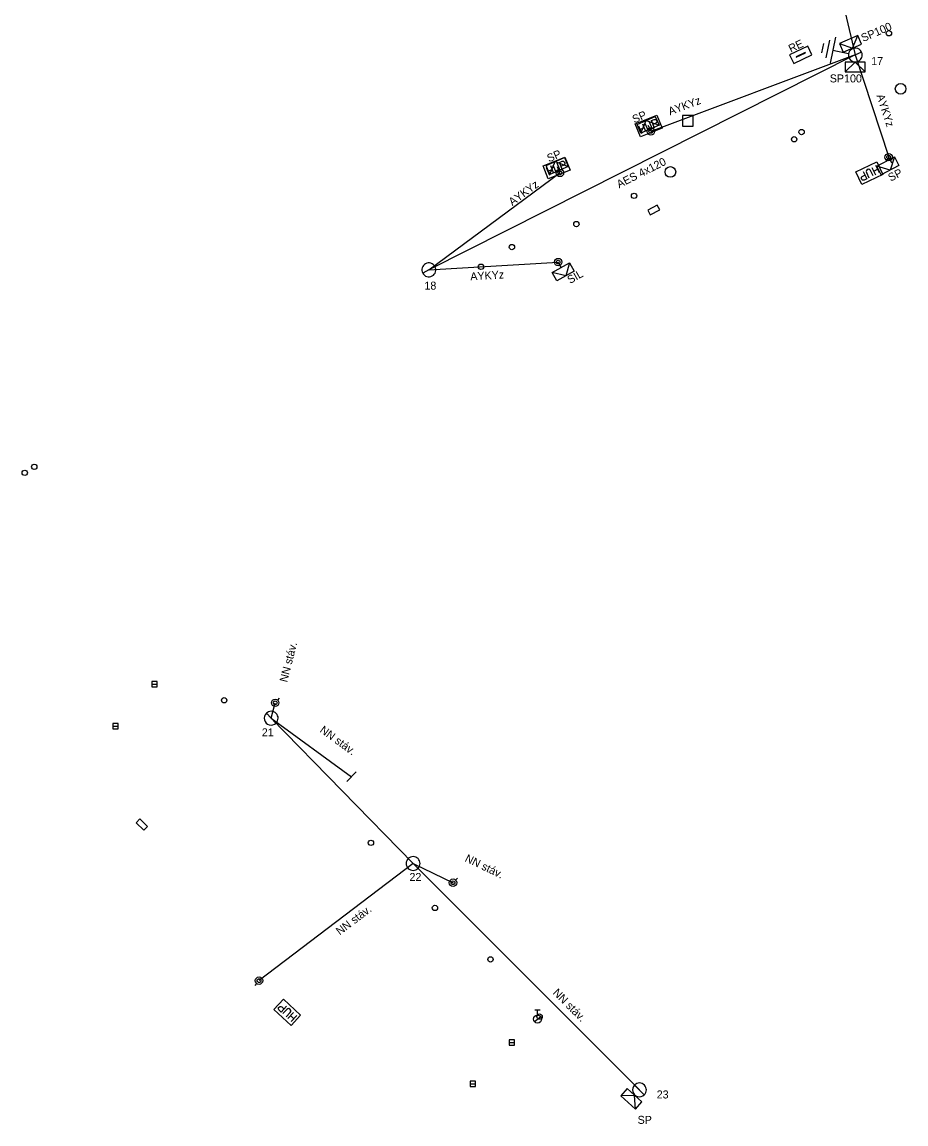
# Model space of a CAD drawing. Extents: x -577028 to -568584, y -1207664 to -1202947.
# Drawn here: x -573558.6 to -573475.8, y -1206499.3 to -1206396.1 of the extents above; entities that cross this region are included whole.
import ezdxf

# ---------------------------------------------------------------- set-up
doc = ezdxf.new("R2010")
doc.units = 0
for name, color, linetype in [('CIZÍ_NADZEM', 7, 'Continuous'), ('ELE_EON', 7, 'Continuous'), ('ELE_EON_POPIS', 7, 'Continuous')]:
    doc.layers.add(name, color=color, linetype=linetype)

msp = doc.modelspace()

# ---------------------------------------------------------------- linework, layer by layer
at = {"layer": 'CIZÍ_NADZEM'}
for p, q in [((-573495.72, -1206404.81), (-573496.72, -1206404.81)), ((-573496.72, -1206404.81), (-573496.72, -1206405.81)), ((-573495.72, -1206405.81), (-573495.72, -1206404.81)), ((-573496.72, -1206405.81), (-573495.72, -1206405.81)), ((-573546.45, -1206458.12), (-573545.95, -1206458.12)), ((-573550.11, -1206462.06), (-573549.61, -1206462.06)), ((-573510.55, -1206488.64), (-573510.05, -1206488.64)), ((-573510.3, -1206489.14), (-573510.3, -1206488.64)), ((-573510.59, -1206489.74), (-573510, -1206489.28)), ((-573512.95, -1206491.71), (-573512.45, -1206491.71)), ((-573516.6, -1206495.58), (-573516.1, -1206495.58))]:
    msp.add_line(p, q, dxfattribs=at)
for points in [[(-573501.16, -1206405.61), (-573499.12, -1206404.78), (-573498.62, -1206406.01), (-573500.66, -1206406.83), (-573501.16, -1206405.61)], [(-573500.24, -1206405.53), (-573500.03, -1206406.05), (-573499.96, -1206406.13), (-573499.87, -1206406.18), (-573499.77, -1206406.18), (-573499.71, -1206406.15), (-573499.64, -1206406.08), (-573499.61, -1206405.99), (-573499.62, -1206405.88), (-573499.83, -1206405.37)], [(-573499.62, -1206405.29), (-573499.36, -1206405.18), (-573499.26, -1206405.18), (-573499.22, -1206405.2), (-573499.16, -1206405.25), (-573499.12, -1206405.36), (-573499.12, -1206405.44), (-573499.14, -1206405.48), (-573499.21, -1206405.55), (-573499.47, -1206405.66)], [(-573499.34, -1206406), (-573499.62, -1206405.29)], [(-573500.85, -1206405.78), (-573500.56, -1206406.5)], [(-573500.71, -1206406.12), (-573500.3, -1206405.95)], [(-573500.15, -1206406.33), (-573500.44, -1206405.62)], [(-573509.78, -1206409.53), (-573507.74, -1206408.72), (-573507.25, -1206409.94), (-573509.29, -1206410.76), (-573509.78, -1206409.53)], [(-573508.78, -1206410.26), (-573509.06, -1206409.54)], [(-573508.86, -1206409.46), (-573508.66, -1206409.97), (-573508.59, -1206410.06), (-573508.5, -1206410.11), (-573508.4, -1206410.11), (-573508.34, -1206410.08), (-573508.27, -1206410.01), (-573508.24, -1206409.92), (-573508.25, -1206409.81), (-573508.45, -1206409.3)], [(-573508.25, -1206409.22), (-573507.98, -1206409.11), (-573507.88, -1206409.11), (-573507.84, -1206409.13), (-573507.79, -1206409.19), (-573507.74, -1206409.29), (-573507.75, -1206409.37), (-573507.76, -1206409.41), (-573507.84, -1206409.48), (-573508.1, -1206409.59)], [(-573507.96, -1206409.93), (-573508.25, -1206409.22)], [(-573477.93, -1206410.35), (-573479.91, -1206411.3), (-573480.48, -1206410.11), (-573478.5, -1206409.15), (-573477.93, -1206410.35)], [(-573478.24, -1206410.19), (-573478.58, -1206409.5)], [(-573509.48, -1206409.71), (-573509.19, -1206410.42)], [(-573509.34, -1206410.04), (-573508.93, -1206409.88)], [(-573479.44, -1206410.76), (-573479.69, -1206410.89), (-573479.79, -1206410.89), (-573479.84, -1206410.87), (-573479.9, -1206410.82), (-573479.94, -1206410.72), (-573479.95, -1206410.64), (-573479.93, -1206410.6), (-573479.87, -1206410.53), (-573479.61, -1206410.4)], [(-573479.77, -1206410.07), (-573479.44, -1206410.76)], [(-573478.84, -1206410.48), (-573479.08, -1206409.98), (-573479.15, -1206409.9), (-573479.25, -1206409.86), (-573479.35, -1206409.87), (-573479.4, -1206409.89), (-573479.47, -1206409.97), (-573479.5, -1206410.06), (-573479.48, -1206410.17), (-573479.24, -1206410.67)], [(-573478.98, -1206409.69), (-573478.64, -1206410.38)], [(-573478.4, -1206409.86), (-573478.8, -1206410.06)], [(-573533.4, -1206490.11), (-573535.01, -1206488.6), (-573534.1, -1206487.64), (-573532.5, -1206489.14), (-573533.4, -1206490.11)], [(-573534.34, -1206488.85), (-573534.54, -1206488.65), (-573534.59, -1206488.56), (-573534.59, -1206488.51), (-573534.56, -1206488.44), (-573534.48, -1206488.36), (-573534.41, -1206488.33), (-573534.36, -1206488.33), (-573534.27, -1206488.36), (-573534.06, -1206488.56)], [(-573533.81, -1206488.29), (-573534.34, -1206488.85)], [(-573533.86, -1206489.3), (-573533.48, -1206488.9), (-573533.43, -1206488.8), (-573533.43, -1206488.7), (-573533.47, -1206488.61), (-573533.51, -1206488.57), (-573533.61, -1206488.53), (-573533.7, -1206488.54), (-573533.8, -1206488.6), (-573534.18, -1206489)], [(-573533.17, -1206488.89), (-573533.7, -1206489.45)], [(-573533.13, -1206489.49), (-573533.45, -1206489.19)], [(-573533.38, -1206489.75), (-573532.85, -1206489.19)]]:
    msp.add_lwpolyline(points, dxfattribs=at)
for points in [[(-573499.73, -1206414.14), (-573498.85, -1206413.67), (-573499.09, -1206413.22), (-573499.97, -1206413.69)], [(-573546.45, -1206458.37), (-573545.95, -1206458.37), (-573545.95, -1206457.87), (-573546.45, -1206457.87)], [(-573550.11, -1206462.31), (-573549.61, -1206462.31), (-573549.61, -1206461.81), (-573550.11, -1206461.81)], [(-573547.92, -1206471.11), (-573547.21, -1206471.81), (-573546.86, -1206471.45), (-573547.57, -1206470.75)], [(-573512.95, -1206491.96), (-573512.45, -1206491.96), (-573512.45, -1206491.46), (-573512.95, -1206491.46)], [(-573516.6, -1206495.83), (-573516.1, -1206495.83), (-573516.1, -1206495.33), (-573516.6, -1206495.33)]]:
    msp.add_lwpolyline(points, close=True, dxfattribs=at)
for centre, radius in [((-573477.37, -1206397.11), 0.25), ((-573476.27, -1206402.32), 0.5), ((-573485.55, -1206406.37), 0.25), ((-573486.25, -1206407.05), 0.25), ((-573497.85, -1206410.11), 0.5), ((-573501.25, -1206412.35), 0.25), ((-573506.66, -1206415), 0.25), ((-573512.7, -1206417.15), 0.25), ((-573515.6, -1206419), 0.25), ((-573557.46, -1206437.75), 0.25), ((-573558.36, -1206438.31), 0.25), ((-573539.67, -1206459.63), 0.25), ((-573525.91, -1206472.99), 0.25), ((-573519.91, -1206479.09), 0.25), ((-573514.71, -1206483.92), 0.25), ((-573510.3, -1206489.51), 0.375), ((-573510.11, -1206489.28), 0.25)]:
    msp.add_circle(centre, radius, dxfattribs=at)
at = {"layer": 'ELE_EON'}
for p, q in [((-573483.51, -1206398.06), (-573483.7, -1206398.94)), ((-573482.94, -1206397.77), (-573483.29, -1206399.43)), ((-573482.37, -1206397.48), (-573482.88, -1206399.93)), ((-573482.62, -1206398.71), (-573481.16, -1206399.02)), ((-573479.93, -1206398.88), (-573481.11, -1206399.42)), ((-573499.82, -1206405.99), (-573499.92, -1206405.76)), ((-573508.33, -1206409.87), (-573508.42, -1206409.64)), ((-573477.23, -1206409.04), (-573477.12, -1206409.26)), ((-573508.2, -1206418.87), (-573508.08, -1206419.09)), ((-573519.91, -1206418.98), (-573521.05, -1206419.6)), ((-573534.65, -1206459.62), (-573534.47, -1206459.44)), ((-573534.81, -1206461.78), (-573535.71, -1206460.84)), ((-573528.17, -1206467.25), (-573527.31, -1206466.35)), ((-573521.5, -1206475.39), (-573522.42, -1206474.47)), ((-573517.98, -1206476.48), (-573517.8, -1206476.3)), ((-573536.63, -1206486.17), (-573536.8, -1206486.36)), ((-573500.3, -1206496.61), (-573501.2, -1206495.69))]:
    msp.add_line(p, q, dxfattribs=at)
for points in [[(-573496.66, -1206330.9), (-573488.24, -1206366.5), (-573480.52, -1206399.15)], [(-573482.01, -1206398.07), (-573480.79, -1206398.52), (-573480.29, -1206397.32)], [(-573480.52, -1206399.15), (-573520.48, -1206419.29)], [(-573480.52, -1206399.15), (-573499.68, -1206406.31), (-573499.75, -1206406.1)], [(-573480.52, -1206399.15), (-573477.39, -1206408.73), (-573477.67, -1206409.14)], [(-573479.58, -1206400.73), (-573480.52, -1206399.83), (-573481.46, -1206400.73)], [(-573500.61, -1206406.48), (-573500.11, -1206405.28), (-573498.89, -1206405.72)], [(-573509.14, -1206410.34), (-573508.64, -1206409.14), (-573507.42, -1206409.6)], [(-573476.83, -1206408.71), (-573477.26, -1206409.94), (-573478.51, -1206409.57)], [(-573520.48, -1206419.29), (-573508.2, -1206410.2), (-573508.28, -1206409.97)], [(-573520.48, -1206419.29), (-573508.36, -1206418.56), (-573508.11, -1206419.08)], [(-573507.3, -1206418.62), (-573507.66, -1206419.86), (-573508.92, -1206419.54)], [(-573535.26, -1206461.31), (-573534.89, -1206459.87)], [(-573535.26, -1206461.31), (-573521.96, -1206474.93), (-573500.75, -1206496.15)], [(-573535.26, -1206461.31), (-573527.74, -1206466.8)], [(-573521.96, -1206474.93), (-573536.4, -1206485.91)], [(-573521.96, -1206474.93), (-573518.22, -1206476.73)], [(-573501.11, -1206497.95), (-573501.21, -1206496.66), (-573502.5, -1206496.7)]]:
    msp.add_lwpolyline(points, dxfattribs=at)
for points in [[(-573481.65, -1206398.9), (-573479.93, -1206398.15), (-573480.29, -1206397.32), (-573482.01, -1206398.07)], [(-573486.29, -1206399.95), (-573484.59, -1206399.15), (-573484.98, -1206398.33), (-573486.67, -1206399.14)], [(-573486.05, -1206399.36), (-573485.2, -1206398.96), (-573485.22, -1206398.93), (-573486.06, -1206399.33)], [(-573479.58, -1206399.83), (-573481.46, -1206399.83), (-573481.46, -1206400.73), (-573479.58, -1206400.73)], [(-573500.97, -1206405.66), (-573499.26, -1206404.9), (-573498.89, -1206405.72), (-573500.61, -1206406.48)], [(-573509.5, -1206409.52), (-573507.78, -1206408.77), (-573507.42, -1206409.6), (-573509.14, -1206410.34)], [(-573476.43, -1206409.52), (-573478.1, -1206410.37), (-573478.51, -1206409.57), (-573476.83, -1206408.71)], [(-573506.85, -1206419.4), (-573508.48, -1206420.33), (-573508.92, -1206419.54), (-573507.3, -1206418.62)], [(-573500.51, -1206497.28), (-573501.9, -1206496.03), (-573502.5, -1206496.7), (-573501.11, -1206497.95)]]:
    msp.add_lwpolyline(points, close=True, dxfattribs=at)
for centre, radius in [((-573499.68, -1206406.31), 0.35), ((-573499.68, -1206406.31), 0.175), ((-573477.39, -1206408.73), 0.35), ((-573477.39, -1206408.73), 0.175), ((-573508.2, -1206410.2), 0.35), ((-573508.2, -1206410.2), 0.175), ((-573508.36, -1206418.56), 0.35), ((-573508.36, -1206418.56), 0.175), ((-573534.89, -1206459.87), 0.35), ((-573534.89, -1206459.87), 0.175), ((-573518.22, -1206476.73), 0.35), ((-573518.22, -1206476.73), 0.175), ((-573536.4, -1206485.91), 0.35), ((-573536.4, -1206485.91), 0.175)]:
    msp.add_circle(centre, radius, dxfattribs=at)
for centre, start, end in [((-573480.52, -1206399.15), 24.9153, 204.9153), ((-573480.52, -1206399.15), 204.9153, 24.9153), ((-573520.48, -1206419.29), 28.1774, 208.1774), ((-573520.48, -1206419.29), 208.1774, 28.1774), ((-573535.26, -1206461.31), 134.319, 314.319), ((-573535.26, -1206461.31), 314.319, 134.319), ((-573521.96, -1206474.93), 134.9865, 314.9865), ((-573521.96, -1206474.93), 314.9865, 134.9865), ((-573500.75, -1206496.15), 134.3414, 314.3414), ((-573500.75, -1206496.15), 314.3414, 134.3414)]:
    msp.add_arc(centre, 0.65, start, end, dxfattribs=at)

# ---------------------------------------------------------------- texts
at = {"layer": 'ELE_EON_POPIS'}
for s, rotation, p in [('SP100', 23.5267, (-573479.78, -1206397.94)), ('RE', 25.4783, (-573486.56, -1206398.94)), ('AYKYz', 20.4905, (-573497.89, -1206404.81)), ('AYKYz', 288.0934, (-573478.54, -1206402.95)), ('SP', 23.8505, (-573501.22, -1206405.57)), ('SP', 23.4166, (-573509.22, -1206409.22)), ('AES 4x120', 26.7483, (-573502.65, -1206411.65)), ('SP', 27.0186, (-573477.21, -1206411.03)), ('AYKYz', 36.5099, (-573512.66, -1206413.32)), ('AYKYz', 3.4468, (-573516.58, -1206420.28)), ('SIL', 29.6731, (-573507.25, -1206420.62)), ('NN stáv.', 75.5899, (-573533.77, -1206457.99)), ('NN stáv.', 323.8686, (-573530.77, -1206462.56)), ('NN stáv.', 334.2993, (-573517.17, -1206474.7)), ('NN stáv.', 37.2489, (-573528.83, -1206481.68)), ('NN stáv.', 314.9865, (-573508.92, -1206487.11))]:
    msp.add_text(s, height=0.75, rotation=rotation, dxfattribs=at).set_placement(p)
for s, p in [('17', (-573479.03, -1206400.1)), ('SP100', (-573482.91, -1206401.72)), ('18', (-573520.9, -1206421.14)), ('21', (-573536.14, -1206463.01)), ('22', (-573522.3, -1206476.57)), ('23', (-573499.13, -1206496.95)), ('SP', (-573500.92, -1206499.33))]:
    msp.add_text(s, height=0.75, dxfattribs=at).set_placement(p)

doc.saveas('drawing.dxf')
